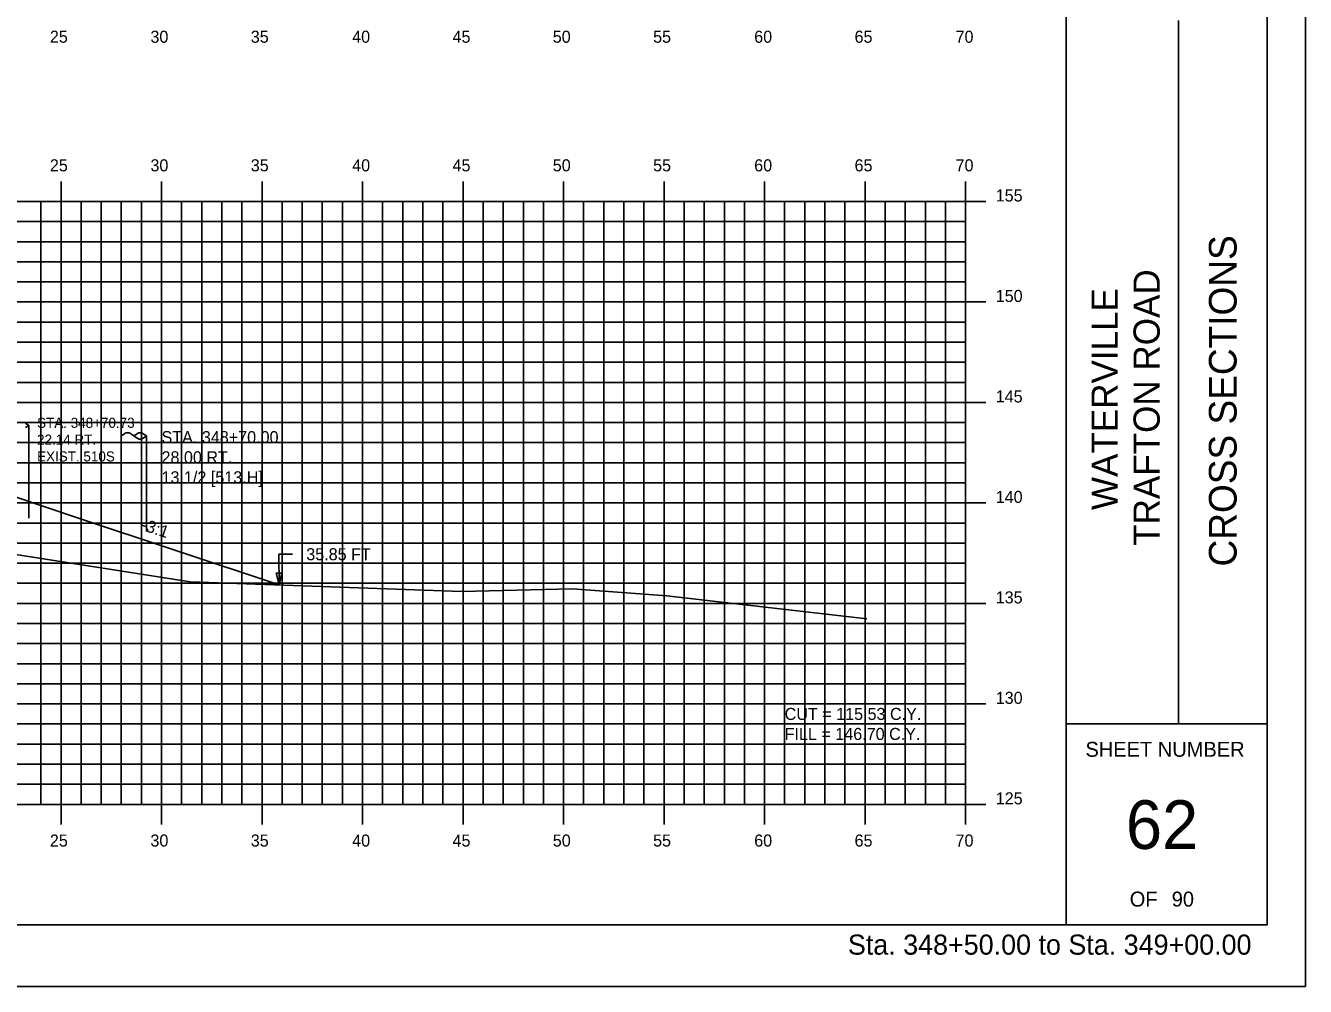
# Model space of a CAD drawing. Extents: x 1144307 to 1144477, y 608981 to 609091.
# Drawn here: x 1144413.3 to 1144477, y 608981.3 to 609029.1 of the extents above; entities that cross this region are included whole.
import ezdxf

# ---------------------------------------------------------------- set-up
doc = ezdxf.new("R2010")
doc.units = 0
for name, color, linetype in [('ANNOTATION', 7, 'Continuous'), ('BORDER', 7, 'Continuous'), ('D_Roadway_SlopeLines', 7, 'Continuous'), ('D_Text_Monospaced', 7, 'Continuous'), ('D_Text_Standard', 7, 'Continuous'), ('D_Utilities_Pole_Joint_Rt', 7, 'Continuous'), ('H_V ANNOTATION', 7, 'Continuous'), ('HIGHWAY_TITLE', 7, 'Continuous'), ('MAJOR', 7, 'Continuous'), ('MINOR', 7, 'Continuous'), ('PLOT BOUNDARY', 7, 'Continuous'), ('S_Roadway_Centerline', 7, 'Continuous'), ('S_Utilities_Pole_Power', 7, 'Continuous')]:
    doc.layers.add(name, color=color, linetype=linetype)

msp = doc.modelspace()

# ---------------------------------------------------------------- linework, layer by layer
msp.add_lwpolyline([(1144347.334, 609012.13), (1144348.584, 609011.953), (1144349.834, 609011.648), (1144351.084, 609011.215), (1144352.334, 609010.654), (1144364.381, 609004.63), (1144367.381, 609005.63), (1144375.105, 609008.205), (1144375.106, 609008.205), (1144379.106, 609008.365), (1144390.106, 609008.585), (1144401.106, 609008.365), (1144405.106, 609008.205), (1144412.829, 609005.631), (1144415.829, 609004.631), (1144425.955, 609001.255)])
at = {"layer": 'BORDER'}
for p, q in [((1144465.106, 608984.335), (1144465.106, 609089.335)), ((1144470.697, 608994.338), (1144470.697, 609029.338)), ((1144465.106, 608994.338), (1144475.106, 608994.338))]:
    msp.add_line(p, q, dxfattribs=at)
msp.add_lwpolyline([(1144315.106, 608984.335), (1144475.106, 608984.335), (1144475.106, 609089.335), (1144315.106, 609089.335)], close=True, dxfattribs=at)
at = {"layer": 'D_Roadway_SlopeLines'}
for points in [[(1144412.829, 609005.631), (1144415.829, 609004.631)], [(1144415.829, 609004.631), (1144425.955, 609001.255)]]:
    msp.add_lwpolyline(points, dxfattribs=at)
at = {"layer": 'D_Text_Standard'}
msp.add_lwpolyline([(1144425.955, 609001.255), (1144425.947, 609002.783), (1144426.627, 609002.783)], dxfattribs=at)
msp.add_lwpolyline([(1144425.955, 609001.255), (1144425.806, 609001.837), (1144426.098, 609001.838)], close=True, dxfattribs=at)
at = {"layer": 'D_Utilities_Pole_Joint_Rt'}
for p, q in [((1144418.106, 609008.668), (1144418.262, 609008.779)), ((1144418.106, 609003.91), (1144418.106, 609008.668)), ((1144418.574, 609008.779), (1144418.73, 609008.668)), ((1144418.887, 609008.779), (1144418.73, 609008.668)), ((1144418.73, 609008.668), (1144418.887, 609008.557)), ((1144419.356, 609008.668), (1144419.2, 609008.779)), ((1144419.2, 609008.557), (1144419.356, 609008.668)), ((1144419.356, 609003.91), (1144419.356, 609008.668))]:
    msp.add_line(p, q, dxfattribs=at)
for centre, start, end in [((1144418.418, 609008.558), 90, 125.26439), ((1144418.418, 609008.558), 54.73561, 90), ((1144419.043, 609008.558), 90, 125.26439), ((1144419.043, 609008.558), 54.73561, 90), ((1144419.043, 609008.779), 234.73561, 270), ((1144419.043, 609008.779), 270, 305.26439)]:
    msp.add_arc(centre, 0.271, start, end, dxfattribs=at)
at = {"layer": 'MAJOR'}
for p, q in [((1144415.106, 609021.337), (1144415.106, 609020.335)), ((1144420.106, 609021.337), (1144420.106, 609020.335)), ((1144425.106, 609021.337), (1144425.106, 609020.335)), ((1144430.106, 609021.337), (1144430.106, 609020.335)), ((1144435.106, 609021.337), (1144435.106, 609020.335)), ((1144440.106, 609021.337), (1144440.106, 609020.335)), ((1144445.106, 609021.337), (1144445.106, 609020.335)), ((1144450.106, 609021.337), (1144450.106, 609020.335)), ((1144455.106, 609021.337), (1144455.106, 609020.335)), ((1144460.106, 609021.337), (1144460.106, 609020.335)), ((1144320.106, 609020.335), (1144460.106, 609020.335)), ((1144320.106, 609020.335), (1144460.106, 609020.335)), ((1144415.106, 608990.335), (1144415.106, 609020.335)), ((1144420.106, 608990.335), (1144420.106, 609020.335)), ((1144425.106, 608990.335), (1144425.106, 609020.335)), ((1144430.106, 608990.335), (1144430.106, 609020.335)), ((1144435.106, 608990.335), (1144435.106, 609020.335)), ((1144440.106, 608990.335), (1144440.106, 609020.335)), ((1144445.106, 608990.335), (1144445.106, 609020.335)), ((1144450.106, 608990.335), (1144450.106, 609020.335)), ((1144455.106, 608990.335), (1144455.106, 609020.335)), ((1144461.108, 609020.335), (1144459.104, 609020.335)), ((1144460.106, 608990.335), (1144460.106, 609020.335)), ((1144460.106, 608990.335), (1144460.106, 609020.335)), ((1144320.106, 609015.335), (1144460.106, 609015.335)), ((1144461.108, 609015.335), (1144459.104, 609015.335)), ((1144320.106, 609010.335), (1144460.106, 609010.335)), ((1144461.108, 609010.335), (1144459.104, 609010.335)), ((1144320.106, 609005.335), (1144460.106, 609005.335)), ((1144461.108, 609005.335), (1144459.104, 609005.335)), ((1144320.106, 609000.335), (1144460.106, 609000.335)), ((1144461.108, 609000.335), (1144459.104, 609000.335)), ((1144320.106, 608995.335), (1144460.106, 608995.335)), ((1144461.108, 608995.335), (1144459.104, 608995.335)), ((1144320.106, 608990.335), (1144460.106, 608990.335)), ((1144320.106, 608990.335), (1144460.106, 608990.335)), ((1144415.106, 608989.333), (1144415.106, 608990.335)), ((1144420.106, 608989.333), (1144420.106, 608990.335)), ((1144425.106, 608989.333), (1144425.106, 608990.335)), ((1144430.106, 608989.333), (1144430.106, 608990.335)), ((1144435.106, 608989.333), (1144435.106, 608990.335)), ((1144440.106, 608989.333), (1144440.106, 608990.335)), ((1144445.106, 608989.333), (1144445.106, 608990.335)), ((1144450.106, 608989.333), (1144450.106, 608990.335)), ((1144455.106, 608989.333), (1144455.106, 608990.335)), ((1144461.108, 608990.335), (1144459.104, 608990.335)), ((1144460.106, 608989.333), (1144460.106, 608990.335))]:
    msp.add_line(p, q, dxfattribs=at)
at = {"layer": 'MINOR'}
for p, q in [((1144414.106, 608990.335), (1144414.106, 609020.335)), ((1144416.106, 608990.335), (1144416.106, 609020.335)), ((1144417.106, 608990.335), (1144417.106, 609020.335)), ((1144418.106, 608990.335), (1144418.106, 609020.335)), ((1144419.106, 608990.335), (1144419.106, 609020.335)), ((1144421.106, 608990.335), (1144421.106, 609020.335)), ((1144422.106, 608990.335), (1144422.106, 609020.335)), ((1144423.106, 608990.335), (1144423.106, 609020.335)), ((1144424.106, 608990.335), (1144424.106, 609020.335)), ((1144426.106, 608990.335), (1144426.106, 609020.335)), ((1144427.106, 608990.335), (1144427.106, 609020.335)), ((1144428.106, 608990.335), (1144428.106, 609020.335)), ((1144429.106, 608990.335), (1144429.106, 609020.335)), ((1144431.106, 608990.335), (1144431.106, 609020.335)), ((1144432.106, 608990.335), (1144432.106, 609020.335)), ((1144433.106, 608990.335), (1144433.106, 609020.335)), ((1144434.106, 608990.335), (1144434.106, 609020.335)), ((1144436.106, 608990.335), (1144436.106, 609020.335)), ((1144437.106, 608990.335), (1144437.106, 609020.335)), ((1144438.106, 608990.335), (1144438.106, 609020.335)), ((1144439.106, 608990.335), (1144439.106, 609020.335)), ((1144441.106, 608990.335), (1144441.106, 609020.335)), ((1144442.106, 608990.335), (1144442.106, 609020.335)), ((1144443.106, 608990.335), (1144443.106, 609020.335)), ((1144444.106, 608990.335), (1144444.106, 609020.335)), ((1144446.106, 608990.335), (1144446.106, 609020.335)), ((1144447.106, 608990.335), (1144447.106, 609020.335)), ((1144448.106, 608990.335), (1144448.106, 609020.335)), ((1144449.106, 608990.335), (1144449.106, 609020.335)), ((1144451.106, 608990.335), (1144451.106, 609020.335)), ((1144452.106, 608990.335), (1144452.106, 609020.335)), ((1144453.106, 608990.335), (1144453.106, 609020.335)), ((1144454.106, 608990.335), (1144454.106, 609020.335)), ((1144456.106, 608990.335), (1144456.106, 609020.335)), ((1144457.106, 608990.335), (1144457.106, 609020.335)), ((1144458.106, 608990.335), (1144458.106, 609020.335)), ((1144459.106, 608990.335), (1144459.106, 609020.335)), ((1144320.106, 609019.335), (1144460.106, 609019.335)), ((1144460.106, 609019.335), (1144459.104, 609019.335)), ((1144320.106, 609018.335), (1144460.106, 609018.335)), ((1144460.106, 609018.335), (1144459.104, 609018.335)), ((1144320.106, 609017.335), (1144460.106, 609017.335)), ((1144460.106, 609017.335), (1144459.104, 609017.335)), ((1144320.106, 609016.335), (1144460.106, 609016.335)), ((1144460.106, 609016.335), (1144459.104, 609016.335)), ((1144320.106, 609014.335), (1144460.106, 609014.335)), ((1144460.106, 609014.335), (1144459.104, 609014.335)), ((1144320.106, 609013.335), (1144460.106, 609013.335)), ((1144460.106, 609013.335), (1144459.104, 609013.335)), ((1144320.106, 609012.335), (1144460.106, 609012.335)), ((1144460.106, 609012.335), (1144459.104, 609012.335)), ((1144320.106, 609011.335), (1144460.106, 609011.335)), ((1144460.106, 609011.335), (1144459.104, 609011.335)), ((1144320.106, 609009.335), (1144460.106, 609009.335)), ((1144460.106, 609009.335), (1144459.104, 609009.335)), ((1144320.106, 609008.335), (1144460.106, 609008.335)), ((1144460.106, 609008.335), (1144459.104, 609008.335)), ((1144320.106, 609007.335), (1144460.106, 609007.335)), ((1144460.106, 609007.335), (1144459.104, 609007.335)), ((1144320.106, 609006.335), (1144460.106, 609006.335)), ((1144460.106, 609006.335), (1144459.104, 609006.335)), ((1144320.106, 609004.335), (1144460.106, 609004.335)), ((1144460.106, 609004.335), (1144459.104, 609004.335)), ((1144320.106, 609003.335), (1144460.106, 609003.335)), ((1144460.106, 609003.335), (1144459.104, 609003.335)), ((1144320.106, 609002.335), (1144460.106, 609002.335)), ((1144460.106, 609002.335), (1144459.104, 609002.335)), ((1144320.106, 609001.335), (1144460.106, 609001.335)), ((1144460.106, 609001.335), (1144459.104, 609001.335)), ((1144320.106, 608999.335), (1144460.106, 608999.335)), ((1144460.106, 608999.335), (1144459.104, 608999.335)), ((1144320.106, 608998.335), (1144460.106, 608998.335)), ((1144460.106, 608998.335), (1144459.104, 608998.335)), ((1144320.106, 608997.335), (1144460.106, 608997.335)), ((1144460.106, 608997.335), (1144459.104, 608997.335)), ((1144320.106, 608996.335), (1144460.106, 608996.335)), ((1144460.106, 608996.335), (1144459.104, 608996.335)), ((1144320.106, 608994.335), (1144460.106, 608994.335)), ((1144460.106, 608994.335), (1144459.104, 608994.335)), ((1144320.106, 608993.335), (1144460.106, 608993.335)), ((1144460.106, 608993.335), (1144459.104, 608993.335)), ((1144320.106, 608992.335), (1144460.106, 608992.335)), ((1144460.106, 608992.335), (1144459.104, 608992.335)), ((1144320.106, 608991.335), (1144460.106, 608991.335)), ((1144460.106, 608991.335), (1144459.104, 608991.335))]:
    msp.add_line(p, q, dxfattribs=at)
at = {"layer": 'PLOT BOUNDARY'}
msp.add_lwpolyline([(1144307.013, 608981.276), (1144477.013, 608981.276), (1144477.013, 609091.276), (1144307.013, 609091.276)], close=True, dxfattribs=at)
at = {"layer": 'S_Roadway_Centerline'}
msp.add_lwpolyline([(1144412.644, 609002.797), (1144421.53, 609001.412), (1144435.029, 609000.934), (1144440.549, 609001.052), (1144445.244, 609000.715), (1144455.191, 608999.561)], dxfattribs=at)
at = {"layer": 'S_Utilities_Pole_Power'}
for p, q in [((1144413.5, 609009.193), (1144413.344, 609009.304)), ((1144413.344, 609009.083), (1144413.5, 609009.193)), ((1144413.5, 609004.574), (1144413.497, 609009.193))]:
    msp.add_line(p, q, dxfattribs=at)

# ---------------------------------------------------------------- texts
at = {"layer": 'ANNOTATION'}
msp.add_text('-3:1', height=0.6, rotation=341.56505, dxfattribs=at).set_placement((1144419.042, 609004.014))
at = {"layer": 'BORDER'}
msp.add_text('CROSS SECTIONS', height=1.37787, rotation=90, dxfattribs=at).set_placement((1144473.59, 609002.172))
for s, height, p in [('SHEET NUMBER', 0.74527, (1144466.071, 608992.701)), ('62', 2.4194, (1144468.082, 608988.118)), ('OF', 0.7453, (1144468.273, 608985.248)), ('90', 0.7453, (1144470.362, 608985.248))]:
    msp.add_text(s, height=height, dxfattribs=at).set_placement(p)
at = {"layer": 'D_Text_Monospaced'}
for s, height, p in [('STA. 348+70.73', 0.49998, (1144413.917, 609009.072)), ('22.14 RT.', 0.5, (1144413.917, 609008.238)), ('EXIST. 510S', 0.49998, (1144413.917, 609007.398))]:
    msp.add_text(s, height=height, dxfattribs=at).set_placement(p)
at = {"layer": 'D_Text_Standard'}
for s, p in [('STA. 348+70.00', (1144420.106, 609008.308)), ('28.00 RT.', (1144420.106, 609007.306)), ('13 1/2 [513.H] ', (1144420.106, 609006.31)), ('35.85 FT', (1144427.307, 609002.483)), ('CUT = 115.53 C.Y.', (1144451.106, 608994.535)), ('FILL = 146.70 C.Y.', (1144451.106, 608993.539))]:
    msp.add_text(s, height=0.6, dxfattribs=at).set_placement(p)
at = {"layer": 'H_V ANNOTATION'}
for s, height, p in [('25', 0.6, (1144414.552, 609028.235)), ('30', 0.6, (1144419.554, 609028.235)), ('35', 0.6, (1144424.546, 609028.235)), ('40', 0.6, (1144429.592, 609028.235)), ('45', 0.6, (1144434.584, 609028.235)), ('50', 0.6, (1144439.57, 609028.235)), ('55', 0.6, (1144444.562, 609028.235)), ('60', 0.6, (1144449.592, 609028.235)), ('65', 0.6, (1144454.584, 609028.235)), ('70', 0.6, (1144459.608, 609028.235)), ('25', 0.6, (1144414.552, 609021.835)), ('30', 0.6, (1144419.554, 609021.835)), ('35', 0.6, (1144424.546, 609021.835)), ('40', 0.6, (1144429.592, 609021.835)), ('45', 0.6, (1144434.584, 609021.835)), ('50', 0.6, (1144439.57, 609021.835)), ('55', 0.6, (1144444.562, 609021.835)), ('60', 0.6, (1144449.592, 609021.835)), ('65', 0.6, (1144454.584, 609021.835)), ('70', 0.6, (1144459.608, 609021.835)), ('155', 0.6, (1144461.606, 609020.335)), ('150', 0.6, (1144461.606, 609015.335)), ('145', 0.6, (1144461.606, 609010.335)), ('140', 0.6, (1144461.606, 609005.335)), ('135', 0.6, (1144461.606, 609000.335)), ('130', 0.6, (1144461.606, 608995.335)), ('125', 0.6, (1144461.606, 608990.335)), ('25', 0.6, (1144414.552, 608988.235)), ('30', 0.6, (1144419.554, 608988.235)), ('35', 0.6, (1144424.546, 608988.235)), ('40', 0.6, (1144429.592, 608988.235)), ('45', 0.6, (1144434.584, 608988.235)), ('50', 0.6, (1144439.57, 608988.235)), ('55', 0.6, (1144444.562, 608988.235)), ('60', 0.6, (1144449.592, 608988.235)), ('65', 0.6, (1144454.584, 608988.235)), ('70', 0.6, (1144459.608, 608988.235)), ('Sta. 348+50.00 to Sta. 349+00.00', 1.0002, (1144454.252, 608982.855))]:
    msp.add_text(s, height=height, dxfattribs=at).set_placement(p)
at = {"layer": 'HIGHWAY_TITLE'}
for s, height, p in [('TRAFTON ROAD', 1.30428, (1144469.765, 609003.201)), ('WATERVILLE', 1.3043, (1144467.678, 609004.98))]:
    msp.add_text(s, height=height, rotation=90, dxfattribs=at).set_placement(p)

doc.saveas('drawing.dxf')
